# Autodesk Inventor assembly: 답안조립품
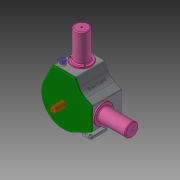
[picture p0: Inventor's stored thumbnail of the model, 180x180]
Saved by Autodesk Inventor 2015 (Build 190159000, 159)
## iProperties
Created: 2022-01
Part Number: 답안조립품
Document SubType Name: Assembly
Designer: user
Mass: 3624.76 g
Surface Area: 4696.85 cm^2
Volume: 1387.05 cm^3
Density: 2.61329 g/cm^3
Author: user
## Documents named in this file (13)
- C:\Users\user\Desktop\620117V1012\답안조립품.iam
- C:\Users\user\Desktop\620117V1012\너트 M3.ipt
- C:\Users\user\Desktop\620117V1012\베어링 20 x 37 x 9.ipt
- C:\Users\user\Desktop\620117V1012\본체.ipt
- C:\Users\user\Desktop\620117V1012\볼트 M3 x 12.ipt
- C:\Users\user\Desktop\620117V1012\실린더.ipt
- C:\Users\user\Desktop\620117V1012\앞커버.ipt
- C:\Users\user\Desktop\620117V1012\축.ipt
- C:\Users\user\Desktop\620117V1012\측정게이지.ipt
- C:\Users\user\Desktop\620117V1012\커넥팅로드 캡.ipt
- C:\Users\user\Desktop\620117V1012\커넥팅로드.ipt
- C:\Users\user\Desktop\620117V1012\피스톤 핀.ipt
- C:\Users\user\Desktop\620117V1012\피스톤.ipt
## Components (4 placed, 2 different names)
1. 피스톤 핀:1
2. 피스톤:1
3. 피스톤:2
4. 피스톤 핀:2
